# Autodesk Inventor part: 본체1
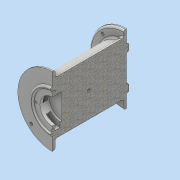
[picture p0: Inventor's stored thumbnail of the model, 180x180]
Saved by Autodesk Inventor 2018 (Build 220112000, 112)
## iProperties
Created: 2024-10
Part Number: 본체1
Material: 일반
Document SubType Name: Modeling
Designer: home
Density: 1 g/cm^3
Appearance: 기본값
Author: home
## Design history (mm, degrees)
sketch "스케치1"
  geometry: C1 r 42 at (0, 0); 1 further point
  constraints: 1 centre point, 1 coincident
  dimensions: "d0" = 84 diameter of C1
extrude "돌출1" new body sketch "스케치1" stored distance "d1" = 122; taper "d2" = 0 deg
sketch "스케치9"
  geometry: C1 r 36 at (0, 0); 1 further point
  constraints: 1 centre point, 1 coincident
  dimensions: "d24" = 72 diameter of C1
extrude "돌출9" join sketch "스케치9" distance "d25" = 3; taper "d26" = 0 deg
sketch "스케치10"
  geometry: C1 r 30 at (0, 0); 1 further point
  constraints: 1 centre point, 1 coincident
  dimensions: "d27" = 60 diameter of C1
extrude "돌출10" cut sketch "스케치10" distance "d28" = 16; taper "d29" = 0 deg
sketch "스케치14"
  geometry: C1 r 58 at (0, 0); 1 further point
  constraints: 1 centre point, 1 coincident
  dimensions: "d52" = 116 diameter of C1
extrude "돌출12" join sketch "스케치14" distance "d53" = 5; taper "d54" = 0 deg
sketch "스케치15"
  geometry: C1 r 58 at (0, 0); 1 further point
  constraints: 1 centre point, 1 coincident
  dimensions: "d55" = 116 diameter of C1
extrude "돌출13" join sketch "스케치15" stored distance "d56" = 5; taper "d57" = 0 deg
sketch "스케치17"
  geometry: C1 r 28 at (0, 0); 5 further points
  constraints: 1 centre point, 1 coincident, 5 other
  dimensions: "d59" = 56 diameter of C1; "d60" = 27.5 distance of point (0, 0) point (0, -27.5); "d63" = 360 deg dimension on C1.centre point (0, -27.5) (derived)
hole "구멍2" sketch "스케치17" at (0, -27.5), (27.5, 0), (0, 27.5), (-27.5, 0) diameter "d65" = 3.459; stored, may be unused: countersink angle "d69" = 90 deg, drill point angle "d71" = 118 deg; dims "d66" = 10, "d67" = 4, "d68" = 2, "d70" = 12
sketch "스케치18"
  geometry: C1 r 21 at (0, 0); 1 further point
  constraints: 1 centre point, 1 coincident
  dimensions: "d72" = 42 diameter of C1
extrude "돌출14" cut sketch "스케치18" distance "d73" = 16; taper "d74" = 0 deg
sketch "스케치19"
  geometry: C1 r 36 at (0, 0); 1 further point
  constraints: 1 centre point, 1 coincident
  dimensions: "d75" = 72 diameter of C1
extrude "돌출15" join sketch "스케치19" distance "d76" = 4; taper "d77" = 0 deg
sketch "스케치20"
  geometry: C1 r 23 at (0, 0); 1 further point
  constraints: 1 centre point, 1 coincident
  dimensions: "d78" = 46 diameter of C1
extrude "돌출16" cut sketch "스케치20" distance "d79" = 4; taper "d80" = 0 deg
sketch "스케치22"
  geometry: L1 (0, 58)-(0, -58); L2 (-58, 0)-(58, 0); L3 (0, 0)-(-35.355, 35.355); L4 (0, 0)-(35.355, 35.355); L5 (0, 0)-(-35.355, -35.355); L6 (0, 0)-(35.355, -35.355); A1 r 50 centre (0, 0) between (-35.355, 35.355) and (35.355, 35.355); A2 r 58 centre (0, 0) between (0, 58) and (0, -58) reference; 5 further points
  constraints: 12 end point, 9 point on circle, 4 coincident, 1 centre point, 1 horizontal
  dimensions: "d81" = 100 diameter of A1; "d82" = 45 deg angle of L2 L3; "d83" = 45 deg angle of L4 L1; "d84" = 45 deg angle of L5 L2; "d85" = 45 deg angle of L6 L1
hole "구멍3" sketch "스케치22" at (-35.355, 35.355), (35.355, 35.355), (-35.355, -35.355), (39.606, -30.519) diameter "d86" = 5.134; stored, may be unused: countersink angle "d90" = 90 deg, drill point angle "d92" = 118 deg; dims "d87" = 12, "d88" = 4, "d89" = 2, "d91" = 14
sketch "스케치23"
  geometry: 1 further point
fillet "모깎기1" dims "d93" = 3
fillet "모깎기2" dims "d94" = 3
sketch "스케치24"
  geometry: L1 (0, -58.694)-(0, 59.557); L2 (58, 0)-(-58, 0); L3 (0, 0)-(35.355, -35.355); L4 (0, 0)-(-35.355, -35.355); L5 (0, 0)-(35.355, 35.355); L6 (0, 0)-(-35.355, 35.355); A1 r 50 centre (0, 0) between (35.355, -35.355) and (-35.355, -35.355); A2 r 58 centre (0, 0) between (58, 0) and (-58, 0) reference; 5 further points
  constraints: 12 end point, 6 point on circle, 5 coincident, 1 centre point, 1 vertical
  dimensions: "d95" = 100 diameter of A1; "d98" = 45 deg angle of L1 L3; "d99" = 45 deg angle of L4 L1; "d100" = 45 deg angle of L1 L5; "d101" = 45 deg angle of L6 L1
hole "구멍4" sketch "스케치24" at (35.355, -35.355), (-35.355, -35.355), (35.355, 35.355) diameter "d102" = 5.134; stored, may be unused: countersink angle "d106" = 90 deg, drill point angle "d108" = 118 deg; dims "d103" = 12, "d104" = 4, "d105" = 2, "d107" = 14
node "작업 평면2"
sketch "스케치26"
  geometry: L1 (-34.659, 25.289)-(-21, 0); L2 (-25.259, 27.666)-(-15.8, 13.833); C1 r 36 at (0, 0) reference; A1 r 5 centre (-30.259, 27.666) between (-25.259, 27.666) and (-34.659, 25.289); A2 r 21 centre (0, 0) between (-21, 0) and (-15.8, 13.833) reference; 1 further point
  constraints: 4 end point, 4 point on circle, 2 tangent, 1 centre point
  dimensions: "d110" = 10 diameter of A1
extrude "돌출17" join sketch "스케치26" extent not by distance; stored distance "d111" = 4; taper "d112" = 0 deg
sketch "스케치31"
  geometry: L1 (-6.991, -39.914)-(-6.991, -19.802); L2 (7.009, -39.914)-(7.009, -19.796); A1 r 7 centre (0.009, -39.914) between (-6.991, -39.914) and (7.009, -39.914); A2 r 21 centre (0, 0) between (-6.991, -19.802) and (7.009, -19.796) reference; 1 further point
  constraints: 4 end point, 4 point on circle, 2 vertical, 1 centre point, 1 tangent
  dimensions: "d119" = 14 diameter of A1
extrude "돌출19" join sketch "스케치31" extent not by distance; stored distance "d120" = 4; taper "d121" = 0 deg
fillet "모깎기3" dims "d122" = 3
fillet "모깎기4" dims "d123" = 3
node "작업 평면4"
sketch "스케치32"
  geometry: C1 r 7.5 at (0, 0); 1 further point
  constraints: 1 centre point, 1 coincident
  dimensions: "d125" = 15 diameter of C1
extrude "돌출20" join sketch "스케치32" stored distance "d126" = 4; taper "d127" = 0 deg
fillet "모깎기5" dims "d128" = 3
hole "구멍5" diameter "d131" = 5.188; stored, may be unused: countersink angle "d135" = 90 deg, drill point angle "d137" = 0 deg; dims "d129" = 10, "d130" = 10, "d132" = 12, "d133" = 4, "d134" = 2, "d136" = 16
node "작업 평면5"
sketch "스케치34"
  geometry: 2 further points
  constraints: 1 other
feature "엠보싱1" sketch "스케치34" dims "d139" = 0.5, "d140" = 0
fillet "모깎기6" dims "d141" = 3
chamfer "모따기1" distance "d142" = 2; stored, may be unused: second distance "d143" = 2, angle "d144" = 45 deg
node "솔리드1"
mirror "미러1"
other parameters: "d109" = -15, "d138" = -62
